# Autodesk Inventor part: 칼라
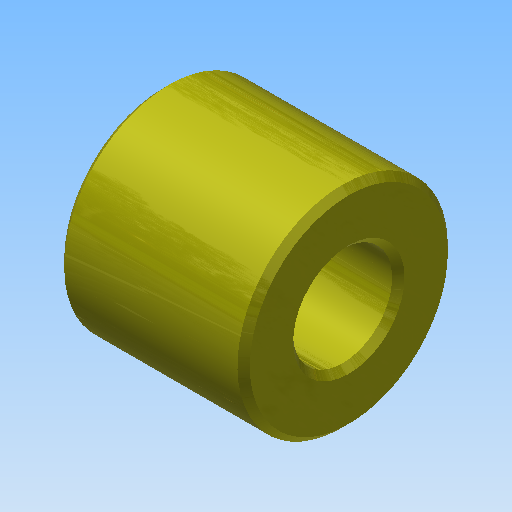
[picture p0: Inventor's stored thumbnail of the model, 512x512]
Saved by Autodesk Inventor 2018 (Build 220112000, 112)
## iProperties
Created: 2022-09
Part Number: 칼라
Material: 강철, 연강
Document SubType Name: Modeling
Designer: mdu-01
Density: 7.86 g/cm^3
Mass: 20.6803 g
Surface Area: 14.8552 cm^2
Volume: 2.63108 cm^3
Appearance: 노란색
Author: mdu-01
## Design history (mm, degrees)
sketch "스케치1"
  geometry: L1 (0, 0)-(15, 0); L2 (15, 0)-(15, 4); L3 (15, 8.5)-(0, 8.5); L4 (0, 8.5)-(0, 4); L5 (0, 4)-(15, 4); L6 (0, 4)-(0, 0); L7 (15, 4)-(15, 8.5); 1 further point
  constraints: 14 end point, 5 parallel, 4 perpendicular, 1 coincident, 1 horizontal
  dimensions: "d0" = 15 distance between parallel lines of L4 L2; "d2" = 17 diameter of L3 L1; "d3" = 8 diameter of L5 L1
revolve "회전1" sketch "스케치1" stored, may be unused: angle "d4" = 90 deg
chamfer "모따기1" distance "d5" = 0.5; stored, may be unused: second distance "d6" = 2, angle "d7" = 45 deg
node "솔리드1"
